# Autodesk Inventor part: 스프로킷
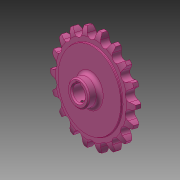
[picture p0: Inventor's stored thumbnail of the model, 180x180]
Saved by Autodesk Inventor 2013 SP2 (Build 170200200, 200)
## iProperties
Created: 2016-03
Part Number: 스프로킷
Material: 강철, 탄소
Document SubType Name: Modeling
Designer: mduedu
Density: 7.87 g/cm^3
Mass: 301.818 g
Surface Area: 124.882 cm^2
Volume: 38.3505 cm^3
Author: mduedu
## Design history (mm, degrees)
sketch "스케치1"
  geometry: L1 (0, 5)-(29.5, 5); L2 (29.5, 5)-(29.5, 4.1); L3 (30, 3.6)-(33.625, 3.6); L4 (40, 2)-(40, 0); L5 (40, 0)-(0, 0); L6 (0, 0)-(0, 5); L7 (0, -5)-(29.5, -5); L8 (29.5, -5)-(29.5, -4.1); L9 (30, -3.6)-(33.625, -3.6); L10 (40, -2)-(40, 0); L11 (0, 0)-(0, -5); A1 r 13.5 centre (33.625, -9.9) between (40, 2) and (33.625, 3.6); A2 r 13.5 centre (33.625, 9.9) between (33.625, -3.6) and (40, -2); A3 r 0.5 centre (30, 4.1) between (29.5, 4.1) and (30, 3.6); A4 r 0.5 centre (30, -4.1) between (30, -3.6) and (29.5, -4.1); 2 further points
  constraints: 22 end point, 8 point on circle, 6 symmetric about line, 5 tangent, 4 centre point, 4 parallel, 4 point on line, 1 equal radius, 1 horizontal, 1 perpendicular, 1 other
  dimensions: "d0" = 80 diameter of L4 L6; "d2" = 59 diameter of L2 L6; "d3" = 1.6 vertical distance of L4.start L3.end; "d4" = 3.6 distance from line of L4.end L3; "d5" = 5 distance between parallel lines of L5 L1; "d6" = 13.5 radius of A1; "d15" = 0.5 radius of A3
revolve "회전1" sketch "스케치1" stored, may be unused: angle "d7" = 90 deg
sketch "스케치2" dims "d8" = 65.2, "d11" = 80
  geometry: L1 (0, 0)-(0, 32.6); A1 r 36.57 centre (0, 0) between (-16.231, 32.771) and (0, 36.57); A2 r 3.97 centre (0, 36.57) between (-3.866, 35.665) and (0, 32.6); A3 r 12.7 centre (-16.231, 32.771) between (-3.866, 35.665) and (-5.534, 39.615); A4 r 12.7 centre (16.231, 32.771) between (5.534, 39.615) and (3.866, 35.665); A5 r 3.97 centre (0, 36.57) between (0, 32.6) and (3.866, 35.665); A6 r 40 centre (0, 0) between (5.534, 39.615) and (-5.534, 39.615); 2 further points
  constraints: 12 point on circle, 6 centre point, 4 coincident, 3 symmetric about line, 2 end point, 1 point on line, 1 tangent, 1 vertical, 1 vertical alignment, 7 other
  dimensions: "d10" = 73.14 diameter of A1; "d12" = 12.7 radius of A3
extrude "돌출1" cut sketch "스케치2" stored distance "d13" = 10; taper "d14" = 0 deg
sketch "스케치3"
  geometry: C1 r 10 at (0, 0); 1 further point
  constraints: 1 centre point, 1 coincident
  dimensions: "d19" = 20 diameter of C1
extrude "돌출2" join sketch "스케치3" distance "d20" = 9; taper "d21" = 0 deg
fillet "모깎기1" dims "d22" = 3
sketch "스케치4"
  geometry: L1 (-2, 0)-(2, 0); L2 (2, 0)-(2, 7.8); L3 (2, 7.8)-(-2, 7.8); L4 (-2, 7.8)-(-2, 0); C1 r 6 at (0, 0); 2 further points
  constraints: 8 end point, 2 coincident, 2 parallel, 1 centre point, 1 horizontal, 1 midpoint, 1 perpendicular
  dimensions: "d23" = 12 diameter of C1; "d25" = 4 distance of L2.end L3.end; "d26" = 7.8 distance of L1.end L2.end
extrude "돌출3" cut sketch "스케치4" stored distance "d27" = 8; taper "d28" = 0 deg
chamfer "모따기2" distance "d42" = 1; stored, may be unused: second distance "d43" = 2, angle "d44" = 45 deg
node "작업 평면2"
sketch "스케치6"
  geometry: L1 (-9, 14)-(9, 14) reference; 3 further points
  constraints: 2 vertical alignment, 1 midpoint
  dimensions: "d59" = 4 distance from line of point (0, 10) L1
hole "구멍2" sketch "스케치6" at (0, 10) diameter "d48" = 3; stored, may be unused: countersink angle "d52" = 90 deg, drill point angle "d54" = 118 deg; dims "d49" = 6, "d50" = 4, "d51" = 2, "d53" = 8
thread "Thread1" dims "d56" = 10, "d57" = 0
node "솔리드1"
pattern_circular "원형 패턴1" dims angle "d17" = 360 deg
other parameters: "d55" = -13
